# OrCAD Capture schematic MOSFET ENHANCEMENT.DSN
size A
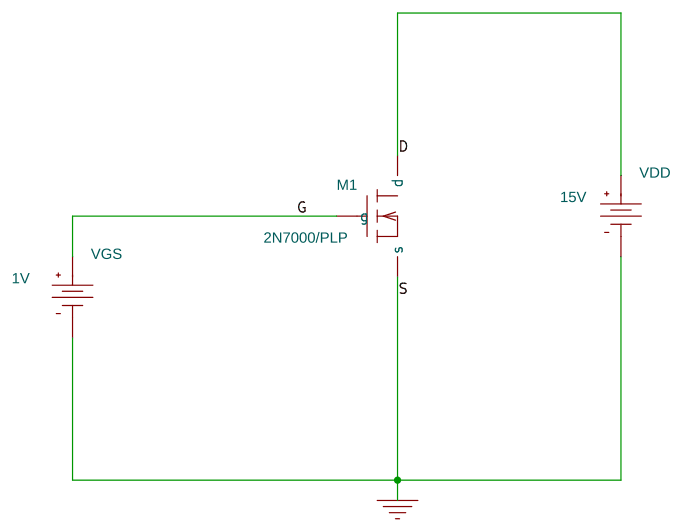
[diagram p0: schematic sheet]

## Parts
M1  2N7000/PLP  [TO92]
VDD  VDC
VGS  VDC

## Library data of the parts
M1 = 2N7000_PLP
VDD = VDC: DC: 15V
VGS = VDC: DC: 1V

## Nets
0: M1.1(s) VDD.1(-) VGS.1(-)
D: M1.3(d) VDD.0(+)
G: M1.2(g) VGS.0(+)
